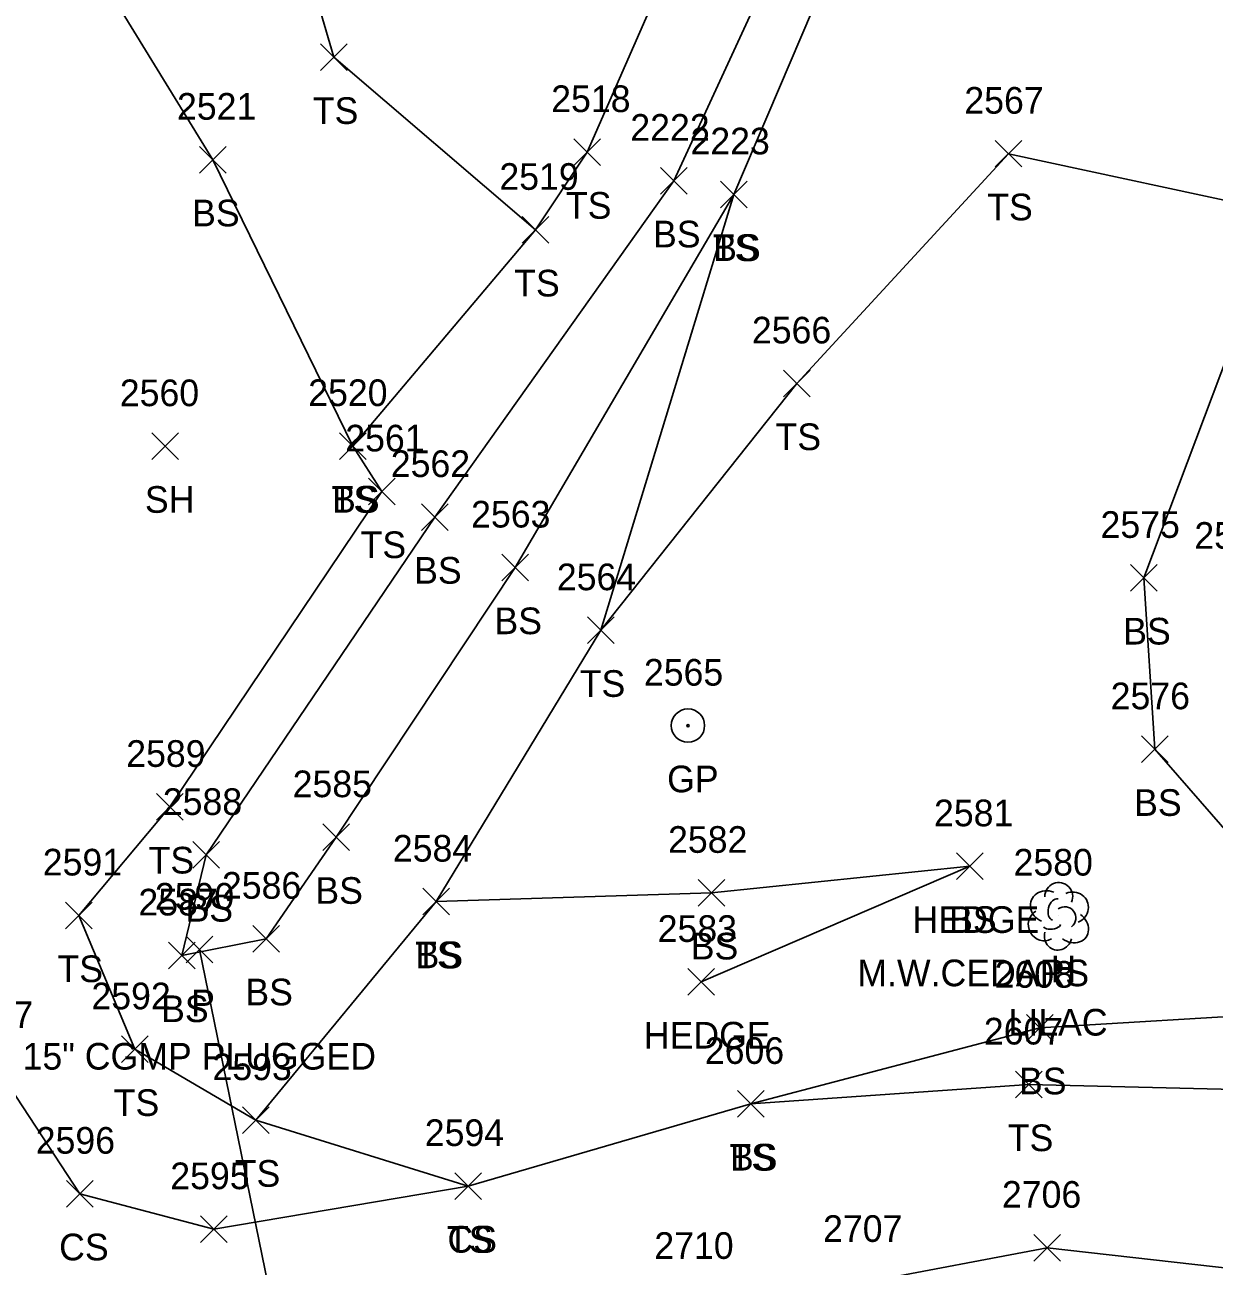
# Model space of a CAD drawing. Extents: x 1520648 to 1523413, y 732854 to 735518.
# Drawn here: x 1521920.9 to 1522010.1, y 733533.8 to 733626.9 of the extents above; entities that cross this region are included whole.
import ezdxf

# ---------------------------------------------------------------- set-up
doc = ezdxf.new("R2010")
doc.units = 0
for name, color, linetype in [('D_A', 7, 'Continuous'), ('D_C', 7, 'Continuous'), ('D_I', 7, 'Continuous'), ('D_TIC', 7, 'Continuous'), ('DCP', 7, 'Continuous'), ('L_A', 7, 'Continuous'), ('L_C', 7, 'Continuous'), ('L_I', 7, 'Continuous'), ('L_TIC', 7, 'Continuous'), ('LAHR', 7, 'Continuous'), ('LELB', 7, 'Continuous'), ('LTD', 7, 'Continuous'), ('R_A', 7, 'Continuous'), ('R_I', 7, 'Continuous'), ('RGP', 7, 'Continuous')]:
    doc.layers.add(name, color=color, linetype=linetype)

msp = doc.modelspace()

# ---------------------------------------------------------------- linework, layer by layer
at = {"layer": 'D_TIC'}
for points in [[(1521933.029, 733556.529), (1521935.029, 733558.529)], [(1521935.029, 733556.529), (1521933.029, 733558.529)]]:
    msp.add_lwpolyline(points, dxfattribs=at)
at = {"layer": 'DCP'}
msp.add_lwpolyline([(1521934.029, 733557.529), (1521944.29, 733507.436)], dxfattribs=at)
at = {"layer": 'L_TIC'}
for points in [[(1521943.122, 733623.476), (1521945.122, 733625.476)], [(1521945.122, 733623.476), (1521943.122, 733625.476)], [(1521962.108, 733616.364), (1521964.108, 733618.364)], [(1521964.108, 733616.364), (1521962.108, 733618.364)], [(1521962.108, 733616.364), (1521964.108, 733618.364)], [(1521964.108, 733616.364), (1521962.108, 733618.364)], [(1521993.71, 733616.244), (1521995.71, 733618.244)], [(1521995.71, 733616.244), (1521993.71, 733618.244)], [(1521934.038, 733615.792), (1521936.038, 733617.792)], [(1521936.038, 733615.792), (1521934.038, 733617.792)], [(1521968.609, 733614.212), (1521970.609, 733616.212)], [(1521970.609, 733614.212), (1521968.609, 733616.212)], [(1521973.122, 733613.19), (1521975.122, 733615.19)], [(1521975.122, 733613.19), (1521973.122, 733615.19)], [(1521973.122, 733613.19), (1521975.122, 733615.19)], [(1521975.122, 733613.19), (1521973.122, 733615.19)], [(1521958.229, 733610.531), (1521960.229, 733612.531)], [(1521960.229, 733610.531), (1521958.229, 733612.531)], [(1521958.229, 733610.531), (1521960.229, 733612.531)], [(1521960.229, 733610.531), (1521958.229, 733612.531)], [(1521977.831, 733599.005), (1521979.831, 733601.005)], [(1521979.831, 733599.005), (1521977.831, 733601.005)], [(1521930.449, 733594.301), (1521932.449, 733596.301)], [(1521932.449, 733594.301), (1521930.449, 733596.301)], [(1521944.534, 733594.31), (1521946.534, 733596.31)], [(1521946.534, 733594.31), (1521944.534, 733596.31)], [(1521944.534, 733594.31), (1521946.534, 733596.31)], [(1521946.534, 733594.31), (1521944.534, 733596.31)], [(1521946.707, 733590.903), (1521948.707, 733592.903)], [(1521948.707, 733590.903), (1521946.707, 733592.903)], [(1521950.69, 733588.985), (1521952.69, 733590.985)], [(1521952.69, 733588.985), (1521950.69, 733590.985)], [(1521956.714, 733585.196), (1521958.714, 733587.196)], [(1521958.714, 733585.196), (1521956.714, 733587.196)], [(1522003.879, 733584.42), (1522005.879, 733586.42)], [(1522005.879, 733584.42), (1522003.879, 733586.42)], [(1521963.145, 733580.493), (1521965.145, 733582.493)], [(1521965.145, 733580.493), (1521963.145, 733582.493)], [(1521963.145, 733580.493), (1521965.145, 733582.493)], [(1521965.145, 733580.493), (1521963.145, 733582.493)], [(1522004.695, 733571.564), (1522006.695, 733573.564)], [(1522006.695, 733571.564), (1522004.695, 733573.564)], [(1521930.806, 733567.241), (1521932.806, 733569.241)], [(1521932.806, 733567.241), (1521930.806, 733569.241)], [(1521943.282, 733564.966), (1521945.282, 733566.966)], [(1521945.282, 733564.966), (1521943.282, 733566.966)], [(1521933.542, 733563.632), (1521935.542, 733565.632)], [(1521935.542, 733563.632), (1521933.542, 733565.632)], [(1521933.542, 733563.632), (1521935.542, 733565.632)], [(1521935.542, 733563.632), (1521933.542, 733565.632)], [(1521990.82, 733562.784), (1521992.82, 733564.784)], [(1521992.82, 733562.784), (1521990.82, 733564.784)], [(1521990.82, 733562.784), (1521992.82, 733564.784)], [(1521992.82, 733562.784), (1521990.82, 733564.784)], [(1521950.797, 733560.133), (1521952.797, 733562.133)], [(1521952.797, 733560.133), (1521950.797, 733562.133)], [(1521950.797, 733560.133), (1521952.797, 733562.133)], [(1521952.797, 733560.133), (1521950.797, 733562.133)], [(1521971.439, 733560.792), (1521973.439, 733562.792)], [(1521973.439, 733560.792), (1521971.439, 733562.792)], [(1521923.972, 733559.092), (1521925.972, 733561.092)], [(1521925.972, 733559.092), (1521923.972, 733561.092)], [(1521938.031, 733557.349), (1521940.031, 733559.349)], [(1521940.031, 733557.349), (1521938.031, 733559.349)], [(1521931.711, 733556.092), (1521933.711, 733558.092)], [(1521933.711, 733556.092), (1521931.711, 733558.092)], [(1521970.662, 733554.109), (1521972.662, 733556.109)], [(1521972.662, 733554.109), (1521970.662, 733556.109)], [(1521996.059, 733550.673), (1521998.059, 733552.673)], [(1521998.059, 733550.673), (1521996.059, 733552.673)], [(1521928.188, 733549.052), (1521930.188, 733551.052)], [(1521930.188, 733549.052), (1521928.188, 733551.052)], [(1521995.253, 733546.412), (1521997.253, 733548.412)], [(1521997.253, 733546.412), (1521995.253, 733548.412)], [(1521974.379, 733544.956), (1521976.379, 733546.956)], [(1521976.379, 733544.956), (1521974.379, 733546.956)], [(1521974.379, 733544.956), (1521976.379, 733546.956)], [(1521976.379, 733544.956), (1521974.379, 733546.956)], [(1521937.267, 733543.739), (1521939.267, 733545.739)], [(1521939.267, 733543.739), (1521937.267, 733545.739)], [(1521937.267, 733543.739), (1521939.267, 733545.739)], [(1521939.267, 733543.739), (1521937.267, 733545.739)], [(1521953.192, 733538.796), (1521955.192, 733540.796)], [(1521955.192, 733538.796), (1521953.192, 733540.796)], [(1521953.192, 733538.796), (1521955.192, 733540.796)], [(1521955.192, 733538.796), (1521953.192, 733540.796)], [(1521924.065, 733538.22), (1521926.065, 733540.22)], [(1521926.065, 733538.22), (1521924.065, 733540.22)], [(1521934.103, 733535.559), (1521936.103, 733537.559)], [(1521936.103, 733535.559), (1521934.103, 733537.559)], [(1521996.617, 733534.167), (1521998.617, 733536.167)], [(1521998.617, 733534.167), (1521996.617, 733536.167)]]:
    msp.add_lwpolyline(points, dxfattribs=at)
at = {"layer": 'LAHR'}
msp.add_lwpolyline([(1521991.82, 733563.784), (1521971.662, 733555.109)], dxfattribs=at)
at = {"layer": 'LELB'}
for points in [[(1521957.722, 733698.974), (1521974.388, 733689.82), (1521985.192, 733670.143), (1521978.744, 733653.004), (1521963.108, 733617.364), (1521959.229, 733611.531), (1521945.534, 733595.31), (1521947.707, 733591.903), (1521931.806, 733568.241), (1521924.972, 733560.092), (1521929.188, 733550.052), (1521938.267, 733544.739)], [(1522009.899, 733685.403), (1522006.266, 733668.347), (1521996.314, 733652.939), (1521985.105, 733639.989), (1521974.122, 733614.19), (1521957.714, 733586.196), (1521944.282, 733565.966), (1521939.031, 733558.349), (1521932.711, 733557.092), (1521934.542, 733564.632)], [(1521963.108, 733617.364), (1521959.229, 733611.531), (1521944.122, 733624.476), (1521938.133, 733644.921), (1521918.005, 733661.9), (1521900.959, 733668.325), (1521885.45, 733683.539)], [(1521945.534, 733595.31), (1521935.038, 733616.792), (1521914.4, 733650.371), (1521896.155, 733663.594), (1521882.104, 733673.194), (1521877.172, 733667.899)], [(1521998.524, 733671.856), (1521992.171, 733656.174), (1521981.929, 733641.951), (1521969.609, 733615.212), (1521951.69, 733589.985), (1521934.542, 733564.632)], [(1521964.145, 733581.493), (1521978.831, 733600.005), (1521994.71, 733617.244), (1522015.188, 733612.84)], [(1521974.122, 733614.19), (1521964.145, 733581.493), (1521951.797, 733561.133), (1521938.267, 733544.739), (1521954.192, 733539.796), (1521975.379, 733545.956), (1521996.253, 733547.412), (1522018.903, 733546.854)], [(1522015.188, 733612.84), (1522004.879, 733585.42), (1522005.695, 733572.564), (1522014.869, 733562.046), (1522025.762, 733562.294)], [(1521991.82, 733563.784), (1521972.439, 733561.792), (1521951.797, 733561.133)], [(1521954.192, 733539.796), (1521935.103, 733536.559), (1521925.065, 733539.22), (1521918.867, 733548.641), (1521916.398, 733559.51)], [(1521975.379, 733545.956), (1521997.059, 733551.673), (1522015.399, 733552.774), (1522041.688, 733549.341), (1522068.618, 733540.712), (1522094.948, 733529.305), (1522117.011, 733517.464)], [(1522099.441, 733495.165), (1522070.53, 733509.774), (1522047.9, 733524.225), (1522023.083, 733532.271), (1521997.617, 733535.167), (1521984.146, 733532.602), (1521970.93, 733531.328), (1521948.392, 733515.844), (1521939.126, 733510.388), (1521932.91, 733500.502), (1521929.248, 733494.672)]]:
    msp.add_lwpolyline(points, dxfattribs=at)
at = {"layer": 'LTD'}
msp.add_line((1521998.441, 733560.083), (1521998.441, 733560.083), dxfattribs=at)
msp.add_line((1521998.441, 733560.083), (1521998.441, 733560.083), dxfattribs=at)
msp.add_arc((1521998.488, 733561.517), 1.047, 335.52715, 180.95627, dxfattribs=at)
for centre, major_axis, ratio, start_param, end_param in [((1521997.65, 733560.749), (1.21, -0.512), 0.895232, 1.570796, 4.712389), ((1521998.233, 733560.541), (-0.208, -0.792), 0.645439, 3.141593, 6.283185), ((1521999.483, 733560.666), (-1.141, -0.483), 0.949671, 1.570796, 4.712389), ((1521997.358, 733559.374), (0.584, -1.042), 0.959034, 3.141593, 6.283185), ((1521998.941, 733559.916), (-0.5, 0.667), 0.989748, 3.141593, 6.283185), ((1521997.983, 733559.333), (-0.625, -0.083), 0.423636, 0, 3.141593), ((1521999.441, 733559.25), (-1.09, 0.792), 0.841452, 1.570796, 4.712389), ((1521998.442, 733558.583), (0.265, 1.061), 0.942809, 1.570796, 4.712389)]:
    msp.add_ellipse(centre, major_axis=major_axis, ratio=ratio, start_param=start_param, end_param=end_param, dxfattribs=at)
at = {"layer": 'RGP'}
msp.add_line((1521970.675, 733574.334), (1521970.675, 733574.334), dxfattribs=at)
for radius in [1.25, 0.0833]:
    msp.add_circle((1521970.675, 733574.334), radius, dxfattribs=at)

# ---------------------------------------------------------------- texts
at = {"layer": 'D_A'}
msp.add_text('P', height=2, dxfattribs=at).set_placement((1521933.407, 733552.529))
at = {"layer": 'D_C'}
msp.add_text('15" CGMP PLUGGED', height=2, dxfattribs=at).set_placement((1521920.761, 733548.529))
at = {"layer": 'D_I'}
msp.add_text('2590', height=2, dxfattribs=at).set_placement((1521930.683, 733560.529))
at = {"layer": 'L_A'}
for s, p in [('TS', (1521942.532, 733619.476)), ('TS', (1521961.518, 733612.364)), ('TS', (1521961.518, 733612.364)), ('BS', (1521933.478, 733611.792)), ('TS', (1521993.12, 733612.244)), ('BS', (1521968.05, 733610.212)), ('TS', (1521972.531, 733609.19)), ('BS', (1521972.563, 733609.19)), ('TS', (1521957.638, 733606.531)), ('TS', (1521957.638, 733606.531)), ('TS', (1521977.241, 733595.005)), ('SH', (1521929.938, 733590.301)), ('TS', (1521943.944, 733590.31)), ('BS', (1521943.975, 733590.31)), ('TS', (1521946.116, 733586.903)), ('BS', (1521950.131, 733584.985)), ('BS', (1521956.155, 733581.196)), ('BS', (1522003.32, 733580.42)), ('TS', (1521962.554, 733576.493)), ('TS', (1521962.554, 733576.493)), ('BS', (1522004.136, 733567.564)), ('TS', (1521930.216, 733563.241)), ('BS', (1521942.723, 733560.966)), ('BS', (1521932.983, 733559.632)), ('BS', (1521932.983, 733559.632)), ('HEDGE', (1521987.52, 733558.784)), ('BS', (1521990.261, 733558.784)), ('BS', (1521970.88, 733556.792)), ('TS', (1521950.206, 733556.133)), ('BS', (1521950.238, 733556.133)), ('TS', (1521923.381, 733555.092)), ('H', (1521997.874, 733555.083)), ('BS', (1521937.472, 733553.349)), ('BS', (1521931.152, 733552.092)), ('HEDGE', (1521967.363, 733550.109)), ('BS', (1521995.5, 733546.673)), ('TS', (1521927.598, 733545.052)), ('TS', (1521994.662, 733542.412)), ('TS', (1521973.789, 733540.956)), ('BS', (1521973.82, 733540.956)), ('TS', (1521936.676, 733539.739)), ('TS', (1521936.676, 733539.739)), ('CS', (1521923.506, 733534.22)), ('TS', (1521952.601, 733534.796)), ('CS', (1521952.633, 733534.796))]:
    msp.add_text(s, height=2, dxfattribs=at).set_placement(p)
at = {"layer": 'L_C'}
for s, p in [('M.W.CEDARS', (1521983.379, 733554.784)), ('LILAC', (1521994.717, 733551.083))]:
    msp.add_text(s, height=2, dxfattribs=at).set_placement(p)
at = {"layer": 'L_I'}
for s, p in [('2521', (1521932.345, 733619.792)), ('2518', (1521960.415, 733620.364)), ('2518', (1521960.415, 733620.364)), ('2567', (1521991.403, 733620.244)), ('2222', (1521966.349, 733618.212)), ('2223', (1521970.862, 733617.19)), ('2223', (1521970.862, 733617.19)), ('2519', (1521956.528, 733614.531)), ('2519', (1521956.528, 733614.531)), ('2566', (1521975.469, 733603.005)), ('2560', (1521928.056, 733598.301)), ('2520', (1521942.188, 733598.31)), ('2520', (1521942.188, 733598.31)), ('2561', (1521944.967, 733594.903)), ('2562', (1521948.383, 733592.985)), ('2563', (1521954.407, 733589.196)), ('2575', (1522001.619, 733588.42)), ('2574', (1522008.657, 733587.601)), ('2564', (1521960.838, 733584.493)), ('2564', (1521960.838, 733584.493)), ('2576', (1522002.38, 733575.564)), ('2589', (1521928.539, 733571.241)), ('2585', (1521941.022, 733568.966)), ('2588', (1521931.282, 733567.632)), ('2588', (1521931.282, 733567.632)), ('2581', (1521989.127, 733566.784)), ('2581', (1521989.127, 733566.784)), ('2582', (1521969.179, 733564.792)), ('2584', (1521948.537, 733564.133)), ('2584', (1521948.537, 733564.133)), ('2591', (1521922.279, 733563.092)), ('2580', (1521995.095, 733563.083)), ('2586', (1521935.716, 733561.349)), ('2587', (1521929.451, 733560.092)), ('2583', (1521968.402, 733558.109)), ('2608', (1521993.673, 733554.673)), ('2592', (1521925.928, 733553.052)), ('2597', (1521915.607, 733551.641)), ('2607', (1521992.867, 733550.412)), ('2606', (1521971.938, 733548.956)), ('2606', (1521971.938, 733548.956)), ('2593', (1521935.007, 733547.739)), ('2593', (1521935.007, 733547.739)), ('2594', (1521950.932, 733542.796)), ('2594', (1521950.932, 733542.796)), ('2596', (1521921.75, 733542.22)), ('2595', (1521931.843, 733539.559)), ('2706', (1521994.223, 733538.167)), ('2707', (1521980.807, 733535.602)), ('2710', (1521968.15, 733534.328))]:
    msp.add_text(s, height=2, dxfattribs=at).set_placement(p)
at = {"layer": 'R_A'}
msp.add_text('GP', height=2, dxfattribs=at).set_placement((1521969.108, 733569.334))
at = {"layer": 'R_I'}
msp.add_text('2565', height=2, dxfattribs=at).set_placement((1521967.368, 733577.334))

doc.saveas('drawing.dxf')
